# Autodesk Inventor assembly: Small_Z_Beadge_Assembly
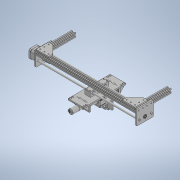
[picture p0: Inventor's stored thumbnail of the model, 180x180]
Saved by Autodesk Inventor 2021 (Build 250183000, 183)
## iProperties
Created: 2026-10
Part Number: Small_Z_Beadge_Assembly
Document SubType Name: Assembly
Designer: hp
Author: hp
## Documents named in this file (15)
- C:\Users\hp\Downloads\Small_Z_Beadge_Assembly.iam
- C:\Users\hp\Downloads\V-Slot 20x20x480 Linear Rail_490.ipt
- C:\Users\hp\Downloads\V-Slot 20x20x250 Linear Rail_150.ipt
- C:\Users\hp\Downloads\V-Slot 20x20x250 Linear Rail_150_1.ipt
- C:\Users\hp\Downloads\l_bracket.ipt
- C:\Users\hp\Downloads\l_bracket_1.ipt
- C:\Users\hp\Downloads\8mm_Bar_500mm.ipt
- C:\Users\hp\Downloads\8mm_Bar_500mm_1.ipt
- C:\Users\hp\Downloads\small_Z_X_Motor_Side.ipt
- C:\Users\hp\Downloads\small_Z_X_Other_Side.ipt
- C:\Users\hp\Downloads\small_Z_Assem1.iam
- C:\Users\hp\Downloads\Nema 17 Stepper Motor.ipt
- C:\Users\hp\Downloads\688_bearing_2.ipt
- C:\Users\hp\Downloads\Flexible Coupling 5mm x 8mm.ipt
- C:\Users\hp\Downloads\Lead Screw T8X8X469.ipt
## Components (14 placed, 11 different names)
1. V-Slot 20x20x480 Linear Rail_490:1
2. V-Slot 20x20x250 Linear Rail_150:1
3. V-Slot 20x20x250 Linear Rail_150:2
4. l_bracket:1
5. l_bracket:2
6. 8mm_Bar_500mm:1
7. 8mm_Bar_500mm:2
8. small_Z_X_Motor_Side:1
9. small_Z_X_Other_Side:1
10. small_Z_Assem1:1 [sub-assembly]
11. Nema 17 Stepper Motor:2
12. 688_bearing:2
13. Flexible Coupling 5mm x 8mm:1
14. Lead Screw T8X8X469:1
